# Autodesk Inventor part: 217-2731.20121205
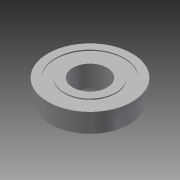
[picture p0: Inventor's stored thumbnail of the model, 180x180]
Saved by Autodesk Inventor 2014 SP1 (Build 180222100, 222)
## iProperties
Created: 2014-06
Part Number: 217-2731.20121205
Material: Steel
Document SubType Name: Modeling
Designer: Michael
Density: 7.85 g/cm^3
Appearance: Steel
Author: svradm
Title: 217-2731.20121205.STEP
Organization: Microsoft
Description: STEP AP203
Creation Date: 2012-12-05
Sending System: SolidWorks 2012
Preprocessor: SwSTEP 2.0
Author: Michael
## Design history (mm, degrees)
node "217-2731.201212051"
node "Revolve1"
node "Base1"
